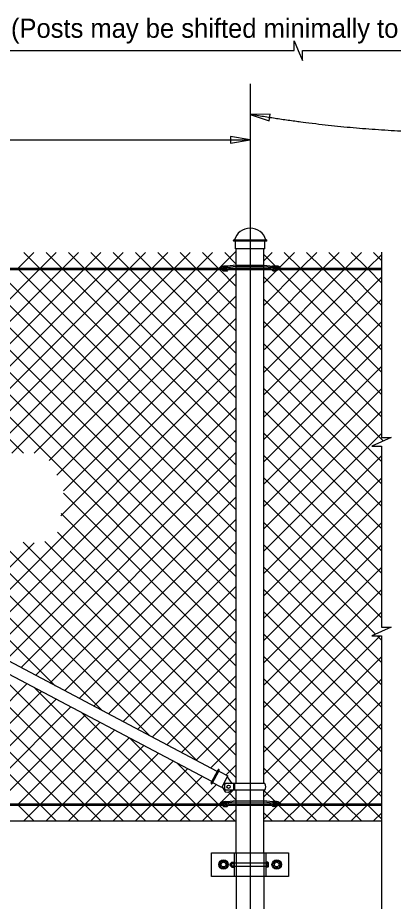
# Model space of a CAD drawing. Extents: x 0 to 41, y -96 to 25.
# Drawn here: x 12.16 to 16.13, y -79.71 to -70.39 of the extents above; entities that cross this region are included whole.
import ezdxf

# ---------------------------------------------------------------- set-up
doc = ezdxf.new("R2010")
doc.units = 0
for name, color, linetype in [('CL_Major', 7, 'Continuous'), ('Dimension', 7, 'Continuous'), ('Miscellaneous', 7, 'Continuous'), ('SteelMisc', 7, 'Continuous'), ('SteelMisc_h', 7, 'Continuous'), ('SupstrConc', 7, 'Continuous'), ('TextStructures', 7, 'Continuous')]:
    doc.layers.add(name, color=color, linetype=linetype)

msp = doc.modelspace()

# ---------------------------------------------------------------- linework, layer by layer
at = {"layer": 'CL_Major'}
msp.add_line((14.615, -71.0824), (14.615, -80.8292), dxfattribs=at)
at = {"layer": 'Dimension'}
for p, q in [((0.2352, -70.732), (13.615, -70.732)), ((4.615, -71.673), (14.615, -71.673))]:
    msp.add_line(p, q, dxfattribs=at)
for points in [[(13.615, -70.732), (15.0787, -70.732), (15.0787, -70.6286), (15.1237, -70.732), (15.1687, -70.8353), (15.1687, -70.732), (28.4596, -70.732)], [(16.002, -72.861), (16.002, -74.8173), (16.1053, -74.8173), (16.002, -74.8623), (15.8987, -74.9073), (16.002, -74.9073), (16.002, -75.8009)], [(16.002, -75.8009), (16.002, -76.8187), (16.1053, -76.8187), (16.002, -76.8637), (15.8987, -76.9087), (16.002, -76.9087), (16.002, -79.113)], [(16.002, -78.863), (16.002, -80.7139), (16.1053, -80.7139), (16.002, -80.7589), (15.8987, -80.8039), (16.002, -80.8039), (16.002, -82.8047)]]:
    msp.add_lwpolyline(points, dxfattribs=at)
for points in [[(14.615, -71.4061), (14.815, -71.4741), (14.8262, -71.4044)], [(14.615, -71.673), (14.4068, -71.6377), (14.4068, -71.7082)]]:
    msp.add_lwpolyline(points, close=True, dxfattribs=at)
msp.add_open_spline([(18.5966, -71.6049), (17.7933, -71.6049), (16.4039, -71.6049), (15.2225, -71.5103), (14.615, -71.4062)], degree=2, dxfattribs=at)
at = {"layer": 'Miscellaneous'}
for p, q in [((12.1661, -73.0298), (12.3328, -72.8631)), ((12.2253, -72.8631), (12.392, -73.0298)), ((12.336, -74.9812), (14.4692, -72.848)), ((12.4018, -73.0298), (12.5685, -72.8631)), ((12.461, -72.8631), (12.6277, -73.0298)), ((12.6375, -73.0298), (12.8042, -72.8631)), ((12.6967, -72.8631), (12.8634, -73.0298)), ((12.8732, -73.0298), (13.0399, -72.8631)), ((12.9324, -72.8631), (13.0991, -73.0298)), ((13.1089, -73.0298), (13.2756, -72.8631)), ((13.1681, -72.8631), (13.3348, -73.0298)), ((13.3446, -73.0298), (13.5113, -72.8631)), ((13.4038, -72.8631), (13.5705, -73.0298)), ((13.5803, -73.0298), (13.747, -72.8631)), ((13.6396, -72.8631), (13.8062, -73.0298)), ((13.816, -73.0298), (13.9827, -72.8631)), ((13.8753, -72.8631), (14.0419, -73.0298)), ((14.0517, -73.0298), (14.2184, -72.8631)), ((14.111, -72.8631), (14.2776, -73.0298)), ((14.2874, -73.0298), (14.4541, -72.8631)), ((14.3467, -72.8631), (14.4692, -72.9857)), ((14.7609, -72.9497), (14.8475, -72.8631)), ((14.7609, -72.8839), (14.8832, -73.0062)), ((14.928, -73.0182), (15.0832, -72.8631)), ((14.9757, -72.8631), (15.1424, -73.0298)), ((15.1522, -73.0298), (15.3189, -72.8631)), ((15.2114, -72.8631), (15.3781, -73.0298)), ((15.3879, -73.0298), (15.5546, -72.8631)), ((15.4471, -72.8631), (15.6138, -73.0298)), ((15.6236, -73.0298), (15.7903, -72.8631)), ((15.6828, -72.8631), (15.8495, -73.0298)), ((15.8593, -73.0298), (16.002, -72.8871)), ((15.9185, -72.8631), (16.002, -72.9465)), ((10.2854, -73.0445), (12.2221, -74.9812)), ((10.4504, -74.9812), (12.3871, -73.0445)), ((10.5211, -73.0445), (14.4692, -76.9926)), ((10.6861, -74.9812), (12.6228, -73.0445)), ((10.7568, -73.0445), (14.4692, -76.7569)), ((10.9218, -74.9812), (12.8585, -73.0445)), ((10.9925, -73.0445), (14.4692, -76.5212)), ((11.1575, -74.9812), (13.0942, -73.0445)), ((11.2282, -73.0445), (14.4692, -76.2855)), ((11.3932, -74.9812), (13.3299, -73.0445)), ((11.4639, -73.0445), (14.4692, -76.0498)), ((11.6289, -74.9812), (13.5656, -73.0445)), ((11.6996, -73.0445), (14.4692, -75.8141)), ((11.8646, -74.9812), (13.8013, -73.0445)), ((11.9353, -73.0445), (14.4692, -75.5784)), ((12.1003, -74.9812), (14.037, -73.0445)), ((12.1711, -73.0445), (14.4692, -75.3427)), ((12.4068, -73.0445), (14.4692, -75.107)), ((12.4951, -75.0578), (14.4692, -73.0837)), ((12.6425, -73.0445), (14.4692, -74.8713)), ((12.8782, -73.0445), (14.4692, -74.6356)), ((13.1139, -73.0445), (14.4692, -74.3999)), ((13.3496, -73.0445), (14.4692, -74.1642)), ((13.5853, -73.0445), (14.4692, -73.9285)), ((13.821, -73.0445), (14.4692, -73.6928)), ((14.0567, -73.0445), (14.4692, -73.4571)), ((14.2924, -73.0445), (14.4692, -73.2214)), ((14.7609, -74.1282), (15.8446, -73.0445)), ((14.7609, -73.6568), (15.3732, -73.0445)), ((14.7609, -73.4211), (15.1375, -73.0445)), ((14.7609, -73.1854), (14.8904, -73.0559)), ((14.7653, -73.888), (15.6089, -73.0445)), ((14.9165, -73.0298), (14.921, -73.0253)), ((14.9214, -73.0445), (16.002, -74.125)), ((15.1572, -73.0445), (16.002, -73.8893)), ((15.3929, -73.0445), (16.002, -73.6536)), ((15.6286, -73.0445), (16.002, -73.4179)), ((15.8643, -73.0445), (16.002, -73.1822)), ((14.7609, -73.1196), (16.002, -74.3607)), ((14.7609, -74.3639), (16.002, -73.1228)), ((12.5756, -75.213), (14.4692, -73.3194)), ((14.7609, -73.3554), (16.002, -74.5964)), ((14.7609, -74.5996), (16.002, -73.3585)), ((12.6439, -75.3804), (14.4692, -73.5551)), ((14.7609, -73.5911), (16.023, -74.8532)), ((14.7609, -74.8353), (16.002, -73.5942)), ((12.6167, -75.6433), (14.4692, -73.7908)), ((14.7609, -73.8268), (16.002, -75.0678)), ((14.7609, -75.071), (16.002, -73.8299)), ((11.5767, -76.919), (14.4692, -74.0265)), ((14.7609, -74.0625), (16.002, -75.3035)), ((14.7609, -75.3067), (16.002, -74.0656)), ((11.7309, -77.0005), (14.4692, -74.2622)), ((14.7609, -74.2982), (16.002, -75.5393)), ((14.7609, -75.5424), (16.002, -74.3013)), ((11.8851, -77.082), (14.4692, -74.4979)), ((14.7609, -74.5339), (16.002, -75.775)), ((14.7609, -75.7781), (16.002, -74.537)), ((12.0393, -77.1635), (14.4692, -74.7336)), ((14.7609, -74.7696), (16.002, -76.0107)), ((14.7609, -76.0138), (16.002, -74.7727)), ((12.1936, -77.245), (14.4692, -74.9693)), ((14.7609, -75.0053), (16.002, -76.2464)), ((14.7609, -76.2495), (16.002, -75.0084)), ((12.3478, -77.3265), (14.4692, -75.205)), ((14.7609, -75.241), (16.002, -76.4821)), ((14.7609, -76.4852), (16.002, -75.2441)), ((12.502, -77.4079), (14.4692, -75.4407)), ((12.6449, -75.404), (14.4692, -77.2283)), ((14.7609, -75.4767), (16.002, -76.7178)), ((14.7609, -76.7209), (16.002, -75.4798)), ((12.6214, -75.6162), (14.4692, -77.464)), ((12.6562, -77.4894), (14.4692, -75.6764)), ((14.7609, -75.7124), (15.9395, -76.8909)), ((14.7609, -76.9566), (16.002, -75.7155)), ((12.5832, -75.8137), (14.4692, -77.6997)), ((12.8104, -77.5709), (14.4692, -75.9121)), ((11.0416, -75.922), (12.5562, -77.4366)), ((11.2773, -75.922), (13.0561, -77.7008)), ((11.4225, -76.8375), (12.3341, -75.9259)), ((11.513, -75.922), (13.5559, -77.9649)), ((11.7487, -75.922), (14.0558, -78.2291)), ((11.9844, -75.922), (14.4692, -78.4068)), ((12.2201, -75.922), (14.4692, -78.1711)), ((12.4479, -75.9141), (14.4692, -77.9354)), ((14.7609, -75.9481), (16.002, -77.1892)), ((14.7609, -77.1923), (16.002, -75.9512)), ((9.8447, -76.1393), (12.3871, -78.6817)), ((12.9646, -77.6524), (14.4692, -76.1478)), ((14.7609, -76.1838), (16.002, -77.4249)), ((14.7609, -77.428), (16.002, -76.1869)), ((10.3445, -76.4034), (12.6228, -78.6817)), ((13.1188, -77.7339), (14.4692, -76.3835)), ((14.7609, -76.4195), (16.002, -77.6606)), ((14.7609, -77.6637), (16.002, -76.4226)), ((13.273, -77.8154), (14.4692, -76.6192)), ((14.7609, -76.6552), (16.002, -77.8963)), ((14.7609, -77.8994), (16.002, -76.6583)), ((10.8444, -76.6676), (12.8585, -78.6817)), ((11.3442, -76.9317), (13.0942, -78.6817)), ((13.4272, -77.8969), (14.4692, -76.8549)), ((14.7609, -76.8909), (16.002, -78.132)), ((14.7609, -78.1351), (15.9873, -76.9087)), ((15.9572, -76.9087), (16.002, -76.9535)), ((13.5814, -77.9784), (14.4692, -77.0906)), ((11.8441, -77.1959), (13.3299, -78.6817)), ((14.7609, -77.1266), (16.002, -78.3677)), ((14.7609, -78.3708), (16.002, -77.1297)), ((13.7356, -78.0599), (14.4692, -77.3263)), ((14.7609, -77.3623), (16.002, -78.6034)), ((14.7609, -78.6065), (16.002, -77.3654)), ((10.9925, -78.6817), (12.2591, -77.4152)), ((11.2282, -78.6817), (12.4133, -77.4966)), ((12.3439, -77.46), (13.5656, -78.6817)), ((11.4639, -78.6817), (12.5675, -77.5781)), ((13.8899, -78.1414), (14.4692, -77.562)), ((11.6996, -78.6817), (12.7217, -77.6596)), ((14.7609, -77.598), (15.8446, -78.6817)), ((14.9303, -78.6728), (16.002, -77.6011)), ((11.9353, -78.6817), (12.8759, -77.7411)), ((12.8437, -77.7241), (13.8013, -78.6817)), ((12.1711, -78.6817), (13.0301, -77.8226)), ((14.0441, -78.2229), (14.4692, -77.7977)), ((14.7609, -77.8337), (15.6089, -78.6817)), ((15.1572, -78.6817), (16.002, -77.8368)), ((12.4068, -78.6817), (13.1843, -77.9041)), ((12.6425, -78.6817), (13.3385, -77.9856)), ((13.3436, -77.9883), (14.037, -78.6817)), ((14.1983, -78.3044), (14.4692, -78.0334)), ((12.8782, -78.6817), (13.4927, -78.0671)), ((13.1139, -78.6817), (13.647, -78.1486)), ((14.7609, -78.0694), (15.3732, -78.6817)), ((15.3929, -78.6817), (16.002, -78.0725)), ((13.3496, -78.6817), (13.8012, -78.2301)), ((13.5853, -78.6817), (13.9554, -78.3116)), ((13.8434, -78.2524), (14.2727, -78.6817)), ((14.36, -78.3783), (14.4692, -78.2691)), ((14.7609, -78.3051), (15.1375, -78.6817)), ((15.6286, -78.6817), (16.002, -78.3083)), ((13.821, -78.6817), (14.1096, -78.3931)), ((14.0567, -78.6817), (14.2591, -78.4792)), ((14.3083, -78.6657), (14.4379, -78.5362)), ((14.3836, -78.5568), (14.4692, -78.6425)), ((14.7609, -78.5408), (14.8783, -78.6582)), ((15.8643, -78.6817), (16.002, -78.544)), ((12.1661, -78.6964), (12.3328, -78.8631)), ((12.2253, -78.8631), (12.392, -78.6964)), ((12.4018, -78.6964), (12.5685, -78.8631)), ((12.461, -78.8631), (12.6277, -78.6964)), ((12.6375, -78.6964), (12.8042, -78.8631)), ((12.6967, -78.8631), (12.8634, -78.6964)), ((12.8732, -78.6964), (13.0399, -78.8631)), ((12.9324, -78.8631), (13.0991, -78.6964)), ((13.1089, -78.6964), (13.2756, -78.8631)), ((13.1681, -78.8631), (13.3348, -78.6964)), ((13.3446, -78.6964), (13.5113, -78.8631)), ((13.4038, -78.8631), (13.5705, -78.6964)), ((13.5803, -78.6964), (13.747, -78.8631)), ((13.6396, -78.8631), (13.8062, -78.6964)), ((13.816, -78.6964), (13.9827, -78.8631)), ((13.8753, -78.8631), (14.0419, -78.6964)), ((14.0517, -78.6964), (14.2184, -78.8631)), ((14.111, -78.8631), (14.2776, -78.6964)), ((14.2874, -78.6964), (14.4541, -78.8631)), ((14.2924, -78.6817), (14.296, -78.6781)), ((14.7609, -78.8422), (14.8992, -78.7039)), ((14.9165, -78.6964), (15.0832, -78.8631)), ((14.9757, -78.8631), (15.1424, -78.6964)), ((15.1522, -78.6964), (15.3189, -78.8631)), ((15.2114, -78.8631), (15.3781, -78.6964)), ((15.3879, -78.6964), (15.5546, -78.8631)), ((15.4471, -78.8631), (15.6138, -78.6964)), ((15.6236, -78.6964), (15.7903, -78.8631)), ((15.6828, -78.8631), (15.8495, -78.6964)), ((15.8593, -78.6964), (16.002, -78.8391)), ((14.3467, -78.8631), (14.4692, -78.7405)), ((14.7641, -78.7798), (14.8475, -78.8631)), ((15.9185, -78.8631), (16.002, -78.7797)), ((14.4075, -79.3301), (14.4075, -79.318)), ((14.4132, -79.3301), (14.4132, -79.318))]:
    msp.add_line(p, q, dxfattribs=at)
at = {"layer": 'SteelMisc'}
for p, q in [((14.4427, -72.7311), (14.7873, -72.7311)), ((14.7873, -72.7434), (14.4427, -72.7434)), ((14.461, -72.8231), (14.461, -72.7434)), ((14.7691, -72.8231), (14.461, -72.8231)), ((14.4692, -78.4683), (14.4692, -72.8231)), ((14.7609, -78.4683), (14.7609, -72.8231)), ((14.7691, -72.8231), (14.7691, -72.7434)), ((14.4692, -72.9972), (14.3743, -73.0082)), ((14.4692, -73.0117), (14.3766, -73.0212)), ((14.4692, -72.9972), (14.7604, -72.9955)), ((14.4692, -73.0117), (14.7604, -73.01)), ((14.7604, -72.9955), (14.8547, -73.0066)), ((14.7604, -73.01), (14.8525, -73.0194)), ((5.8052, -73.0298), (14.2941, -73.0298)), ((5.8052, -73.0445), (14.3207, -73.0445)), ((14.304, -73.0298), (14.3172, -73.0298)), ((14.3856, -73.0445), (14.4692, -73.0445)), ((14.387, -73.0298), (14.4692, -73.0298)), ((14.7609, -73.0298), (14.8413, -73.0298)), ((14.7609, -73.0445), (14.8439, -73.0445)), ((14.9067, -73.0445), (16.002, -73.0445)), ((14.9116, -73.0298), (14.9269, -73.0298)), ((14.9353, -73.0298), (16.002, -73.0298)), ((14.2677, -78.341), (5.0181, -73.453)), ((14.2117, -78.447), (4.962, -73.5591)), ((14.2041, -78.4612), (14.2766, -78.3241)), ((14.216, -78.4675), (14.2885, -78.3304)), ((14.2843, -78.3383), (14.3786, -78.3881)), ((14.3149, -78.5087), (14.3786, -78.3881)), ((14.3744, -78.3961), (14.4213, -78.4679)), ((14.3149, -78.5087), (14.2206, -78.4589)), ((14.3184, -78.5021), (14.3531, -78.5553)), ((14.7722, -78.4683), (14.3525, -78.4683)), ((14.4349, -78.4746), (14.4584, -78.4746)), ((14.4349, -78.4844), (14.4584, -78.4844)), ((14.4349, -78.4961), (14.4584, -78.4961)), ((14.4349, -78.5079), (14.4584, -78.5079)), ((14.4349, -78.5187), (14.4584, -78.5187)), ((14.7721, -78.5361), (14.3525, -78.5361)), ((14.4349, -78.5283), (14.4584, -78.5283)), ((14.4692, -79.1982), (14.4692, -78.5362)), ((14.7609, -79.1982), (14.7609, -78.5362)), ((4.923, -78.6964), (14.3207, -78.6964)), ((4.9243, -78.6817), (14.2941, -78.6817)), ((14.304, -78.6817), (14.3172, -78.6817)), ((14.4692, -78.6491), (14.3743, -78.6602)), ((14.4692, -78.6636), (14.3766, -78.6731)), ((14.3856, -78.6964), (14.4692, -78.6964)), ((14.387, -78.6817), (14.4692, -78.6817)), ((14.4692, -78.6491), (14.7604, -78.6474)), ((14.4692, -78.6636), (14.7604, -78.6619)), ((14.7604, -78.6474), (14.8547, -78.6585)), ((14.7604, -78.6619), (14.8525, -78.6713)), ((14.7609, -78.6817), (14.8413, -78.6817)), ((14.7609, -78.6964), (14.8439, -78.6964)), ((14.9059, -78.6964), (16.002, -78.6964)), ((14.9116, -78.6817), (14.9269, -78.6817)), ((14.9353, -78.6817), (16.002, -78.6817)), ((14.2091, -79.1982), (15.021, -79.1982)), ((14.2091, -79.4482), (14.2091, -79.1982)), ((14.4484, -79.1982), (14.4484, -79.4482)), ((14.7817, -79.1982), (14.7817, -79.4482)), ((15.021, -79.1982), (15.021, -79.4482)), ((14.4047, -79.3152), (14.4103, -79.3086)), ((14.4047, -79.3329), (14.4047, -79.3152)), ((14.4047, -79.3329), (14.4103, -79.3385)), ((14.4103, -79.3086), (14.4168, -79.3086)), ((14.4103, -79.3385), (14.4103, -79.3086)), ((14.4103, -79.3385), (14.4168, -79.3385)), ((14.4168, -79.3053), (14.4168, -79.341)), ((14.4215, -79.3102), (14.4418, -79.3102)), ((14.4215, -79.3361), (14.4418, -79.3361)), ((14.4217, -79.2972), (14.4418, -79.2972)), ((14.4218, -79.3492), (14.4418, -79.3492)), ((14.4418, -79.2929), (14.4418, -79.3535)), ((14.4418, -79.2929), (14.4484, -79.2929)), ((14.4418, -79.2972), (14.4418, -79.3492)), ((14.4418, -79.3535), (14.4484, -79.3535)), ((14.788, -79.2929), (14.782, -79.2929)), ((14.788, -79.3535), (14.782, -79.3535)), ((14.788, -79.2929), (14.788, -79.3535)), ((14.8027, -79.2972), (14.788, -79.2972)), ((14.8028, -79.3102), (14.788, -79.3102)), ((14.8028, -79.3362), (14.788, -79.3362)), ((14.8027, -79.3492), (14.788, -79.3492)), ((14.8078, -79.3426), (14.8078, -79.3037)), ((15.021, -79.4482), (14.2091, -79.4482)), ((14.4692, -79.4482), (14.4692, -80.1982)), ((14.7609, -79.4482), (14.7609, -80.1982))]:
    msp.add_line(p, q, dxfattribs=at)
for points in [[(14.3124, -79.2857), (14.3557, -79.2857), (14.3774, -79.3232), (14.3557, -79.3607), (14.3124, -79.3607), (14.2907, -79.3232)], [(14.8744, -79.2857), (14.9177, -79.2857), (14.9394, -79.3232), (14.9177, -79.3607), (14.8744, -79.3607), (14.8527, -79.3232)]]:
    msp.add_lwpolyline(points, close=True, dxfattribs=at)
for centre, radius in [((14.3341, -79.3232), 0.05), ((14.3341, -79.3232), 0.025), ((14.896, -79.3232), 0.05), ((14.896, -79.3232), 0.025)]:
    msp.add_circle(centre, radius, dxfattribs=at)
for centre, radius, start, end in [((14.4429, -72.7374), 0.00613, 91.1647, 268.8353), ((14.7872, -72.7374), 0.00613, 271.1647, 88.8353), ((14.2827, -78.3271), 0.00673, 332.14902, 152.14902), ((14.2102, -78.4643), 0.00673, 152.14902, 332.14902), ((14.4234, -79.3038), 0.00674, 104.48908, 254.18889), ((14.4363, -79.3232), 0.0196, 138.62797, 221.37203), ((14.4234, -79.3427), 0.00673, 105.7823, 255.54039), ((14.801, -79.3038), 0.00673, 285.7823, 75.54039), ((14.801, -79.3427), 0.00674, 284.48908, 74.18889), ((14.7881, -79.3232), 0.0196, 318.62797, 41.37203)]:
    msp.add_arc(centre, radius, start, end, dxfattribs=at)
for centre, major_axis, ratio, start_param, end_param in [((14.6157, -72.7722), (0.1711, 0), 0.957868, 0.252602, 2.888574), ((14.3283, -73.044), (0.0373, 0), 0.957868, 1.486836, 3.108042), ((14.3494, -73.0837), (-0.0724, 0), 0.957868, 5.162149, 5.652106), ((14.3408, -73.0296), (0.023, 0), 0.957868, 1.29026, 2.970541), ((14.3595, -73.0349), (0.0295, 0), 0.957868, 1.220941, 4.039556), ((14.373, -73.0331), (-0.0303, -0.0108), 0.724765, 4.35367, 6.324556), ((14.3781, -73.0461), (-0.0259, 0), 0.957868, 4.777514, 5.62749), ((14.3626, -73.035), (0.0251, 0), 0.957868, 0.407687, 0.609214), ((14.8661, -73.0333), (-0.0251, 0), 0.957868, 5.673972, 5.875498), ((14.8556, -73.0314), (0.0303, -0.0108), 0.724765, 6.241815, 8.212701), ((14.8506, -73.0443), (0.0259, 0), 0.957868, 0.655696, 1.505671), ((14.8691, -73.0332), (-0.0295, 0), 0.957868, 2.243629, 5.062245), ((14.8879, -73.0278), (-0.023, 0), 0.957868, 3.312645, 4.992926), ((14.9004, -73.0422), (-0.0373, 0), 0.957868, 3.175144, 4.79635), ((14.8792, -73.0819), (0.0724, 0), 0.957868, 0.631079, 1.121037), ((14.3419, -73.0321), (-0.0249, 0), 0.957868, 6.009018, 7.089857), ((14.3433, -73.0361), (0.0231, 0), 0.957868, 3.779554, 4.879821), ((14.3494, -73.0417), (0.0206, -0.0021), 0.798607, 4.32653, 5.220153), ((14.3629, -73.0417), (0.0206, -0.0021), 0.798607, 3.333154, 5.220153), ((14.3697, -73.0372), (-0.0139, 0), 0.957868, 5.22362, 6.905413), ((14.364, -73.0396), (-0.00795, 0), 0.957868, 6.140374, 9.314262), ((14.3624, -73.0338), (0.0119, 0), 0.957868, 5.725876, 7.416677), ((14.3555, -73.023), (0.0391, 0), 0.957868, 5.082588, 5.41974), ((14.3624, -73.0338), (0.0119, 0), 0.957868, 5.639684, 5.723117), ((14.3626, -73.035), (0.0251, 0), 0.957868, 5.531357, 6.227833), ((14.8661, -73.0333), (-0.0251, 0), 0.957868, 0.055352, 0.751829), ((14.8732, -73.0212), (-0.0391, 0), 0.957868, 0.863445, 1.200597), ((14.8663, -73.032), (-0.0119, 0), 0.957868, 5.149694, 6.840495), ((14.8663, -73.032), (-0.0119, 0), 0.957868, 0.560069, 0.643501), ((14.8646, -73.0378), (0.00795, 0), 0.957868, 3.252108, 6.425997), ((14.8658, -73.04), (-0.0206, -0.0021), 0.798607, 1.063032, 2.950031), ((14.859, -73.0354), (0.0139, 0), 0.957868, 5.660958, 7.342751), ((14.8792, -73.04), (-0.0206, -0.0021), 0.798607, 1.063032, 1.956656), ((14.8853, -73.0343), (-0.0231, 0), 0.957868, 1.403365, 2.503632), ((14.8867, -73.0303), (0.0249, 0), 0.957868, 5.476514, 6.557353), ((14.4217, -78.502), (-0.0776, 0), 0.957868, 5.810211, 6.75616), ((14.7031, -78.5021), (0.0776, 0), 0.957868, 5.807767, 6.754779), ((14.3697, -78.487), (0.0647, -0.0342), 0.957868, 4.95193, 6.011789), ((14.3283, -78.6959), (0.0373, 0), 0.957868, 1.486836, 3.108042), ((14.3494, -78.7356), (-0.0724, 0), 0.957868, 5.162149, 5.652106), ((14.3419, -78.684), (-0.0249, 0), 0.957868, 6.009018, 7.089857), ((14.3408, -78.6815), (0.023, 0), 0.957868, 1.29026, 2.970541), ((14.3433, -78.688), (0.0231, 0), 0.957868, 3.779554, 4.879821), ((14.3595, -78.6868), (0.0295, 0), 0.957868, 1.220941, 4.039556), ((14.373, -78.6851), (-0.0303, -0.0108), 0.724765, 4.35367, 6.324556), ((14.3494, -78.6937), (0.0206, -0.0021), 0.798607, 4.32653, 5.220153), ((14.3629, -78.6937), (0.0206, -0.0021), 0.798607, 3.333154, 5.220153), ((14.3697, -78.6891), (-0.0139, 0), 0.957868, 5.22362, 6.905413), ((14.364, -78.6915), (-0.00795, 0), 0.957868, 6.140374, 9.314262), ((14.3781, -78.698), (-0.0259, 0), 0.957868, 4.777514, 5.62749), ((14.3624, -78.6857), (0.0119, 0), 0.957868, 5.725876, 7.416677), ((14.3555, -78.6749), (0.0391, 0), 0.957868, 5.082588, 5.41974), ((14.3624, -78.6857), (0.0119, 0), 0.957868, 5.639684, 5.723117), ((14.3626, -78.687), (0.0251, 0), 0.957868, 5.531357, 6.227833), ((14.3626, -78.687), (0.0251, 0), 0.957868, 0.407687, 0.609214), ((14.8661, -78.6852), (-0.0251, 0), 0.957868, 0.055352, 0.751829), ((14.8661, -78.6852), (-0.0251, 0), 0.957868, 5.673972, 5.875498), ((14.8732, -78.6731), (-0.0391, 0), 0.957868, 0.863445, 1.200597), ((14.8556, -78.6833), (0.0303, -0.0108), 0.724765, 6.241815, 8.212701), ((14.8506, -78.6962), (0.0259, 0), 0.957868, 0.655696, 1.505671), ((14.8663, -78.6839), (-0.0119, 0), 0.957868, 5.149694, 6.840495), ((14.8663, -78.6839), (-0.0119, 0), 0.957868, 0.560069, 0.643501), ((14.8646, -78.6897), (0.00795, 0), 0.957868, 3.252108, 6.425997), ((14.8658, -78.6919), (-0.0206, -0.0021), 0.798607, 1.063032, 2.950031), ((14.8691, -78.6851), (-0.0295, 0), 0.957868, 2.243629, 5.062245), ((14.859, -78.6874), (0.0139, 0), 0.957868, 5.660958, 7.342751), ((14.8792, -78.6919), (-0.0206, -0.0021), 0.798607, 1.063032, 1.956656), ((14.8879, -78.6797), (-0.023, 0), 0.957868, 3.312645, 4.992926), ((14.8853, -78.6862), (-0.0231, 0), 0.957868, 1.403365, 2.503632), ((14.9004, -78.6942), (-0.0373, 0), 0.957868, 3.175144, 4.79635), ((14.8867, -78.6822), (0.0249, 0), 0.957868, 5.476514, 6.557353), ((14.8792, -78.7339), (0.0724, 0), 0.957868, 0.631079, 1.121037)]:
    msp.add_ellipse(centre, major_axis=major_axis, ratio=ratio, start_param=start_param, end_param=end_param, dxfattribs=at)
msp.add_ellipse((14.3884, -78.5016), major_axis=(0.0178, 0), ratio=0.957868, dxfattribs=at)
at = {"layer": 'SteelMisc_h'}
for p, q in [((14.4692, -73.0298), (14.7609, -73.0298)), ((14.4692, -73.0445), (14.7609, -73.0445)), ((14.4692, -78.6817), (14.7609, -78.6817)), ((14.4692, -78.6964), (14.7609, -78.6964)), ((14.4692, -79.1982), (14.4692, -79.4482)), ((14.7609, -79.1982), (14.7609, -79.4482)), ((14.7817, -79.3086), (14.4168, -79.3086)), ((14.4168, -79.3385), (14.7817, -79.3385))]:
    msp.add_line(p, q, dxfattribs=at)
at = {"layer": 'SupstrConc'}
for p, q in [((11.4981, -78.8631), (14.4692, -78.8631)), ((14.7609, -78.8631), (16.002, -78.8631))]:
    msp.add_line(p, q, dxfattribs=at)

# ---------------------------------------------------------------- texts
at = {"layer": 'TextStructures'}
msp.add_text('Equal Spaces @ 10\'-0" Max. (Posts may be shifted minimally to meet required clearances)', height=0.2016, dxfattribs=at).set_placement((8.5826, -70.5974))

doc.saveas('drawing.dxf')
